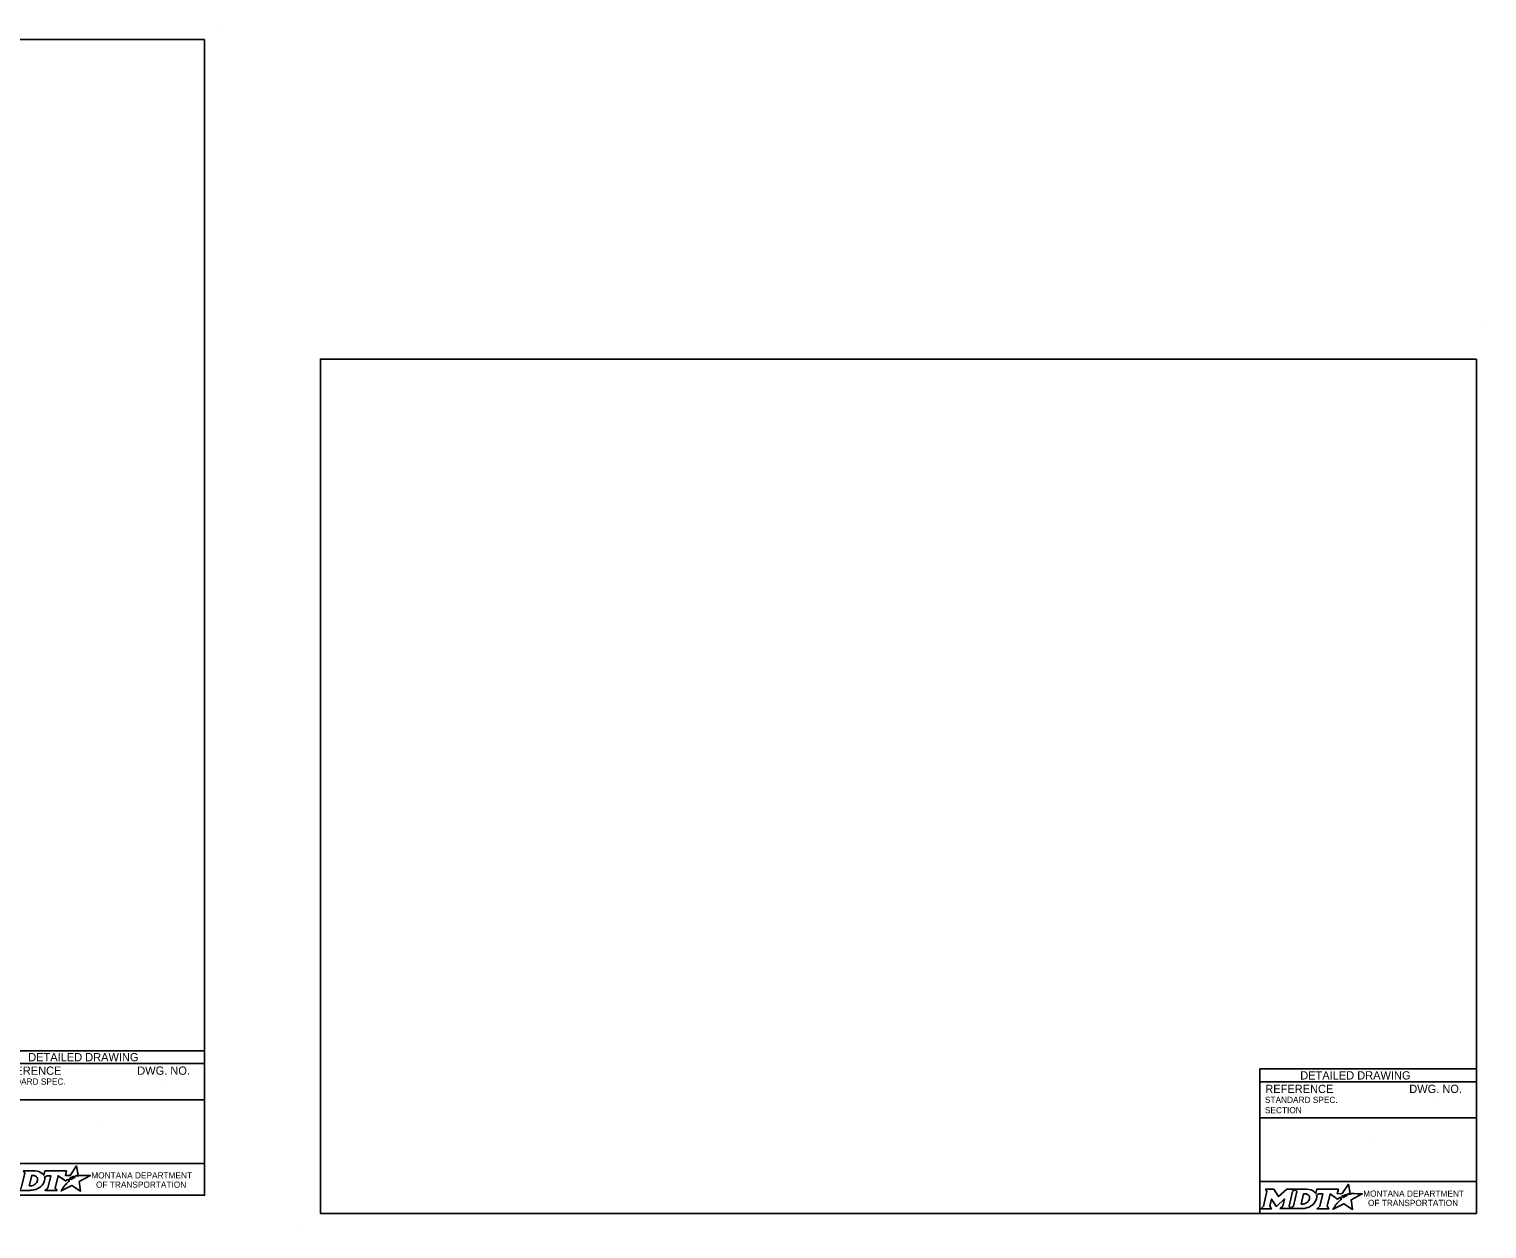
# Model space of a CAD drawing. Extents: x 49991.4 to 50021, y 49987.6 to 50011.4.
# Drawn here: x 50006.92 to 50021.04, y 49999.74 to 50011.36 of the extents above; entities that cross this region are included whole.
import ezdxf

# ---------------------------------------------------------------- set-up
doc = ezdxf.new("R2010")
doc.units = 0
for name, color, linetype in [('Default', 7, 'Continuous'), ('Level 1', 7, 'Continuous'), ('Level 2', 7, 'Continuous'), ('Level 4', 7, 'Continuous')]:
    doc.layers.add(name, color=color, linetype=linetype)

msp = doc.modelspace()

# ---------------------------------------------------------------- linework, layer by layer
at = {"layer": 'Default'}
for points in [[(50019.7, 50000.068), (50019.69, 50000.074), (50019.702, 50000.076), (50019.713, 50000.078), (50019.696, 50000.168), (50019.636, 50000.077), (50019.589, 50000.076), (50019.599, 50000.12), (50019.39, 50000.121), (50019.38, 50000.078), (50019.374, 50000.086)], [(50018.893, 50000.121), (50018.907, 50000.097), (50018.874, 49999.954), (50018.848, 49999.931), (50018.95, 49999.931), (50018.936, 49999.954), (50018.952, 50000.024), (50018.996, 49999.955), (50019.002, 49999.955), (50019.077, 50000.025), (50019.06, 49999.954), (50019.035, 49999.932), (50019.137, 49999.932), (50019.123, 49999.955), (50019.156, 50000.097)], [(50019.156, 50000.097), (50019.182, 50000.121), (50019.099, 50000.121), (50019.02, 50000.048), (50018.975, 50000.12), (50018.893, 50000.121)], [(50019.295, 50000.121), (50019.182, 50000.121), (50019.196, 50000.098), (50019.163, 49999.954), (50019.137, 49999.932), (50019.248, 49999.932)], [(50019.319, 50000.034), (50019.318, 50000.026), (50019.315, 50000.017), (50019.311, 50000.008), (50019.305, 50000.001), (50019.299, 49999.994), (50019.291, 49999.988), (50019.282, 49999.983), (50019.273, 49999.979), (50019.264, 49999.977), (50019.255, 49999.976), (50019.239, 49999.976), (50019.263, 50000.076), (50019.279, 50000.076), (50019.286, 50000.075), (50019.294, 50000.073), (50019.301, 50000.07), (50019.307, 50000.066), (50019.311, 50000.061), (50019.315, 50000.055), (50019.318, 50000.049), (50019.319, 50000.042), (50019.32, 50000.038), (50019.319, 50000.034)], [(50019.387, 50000.062), (50019.411, 50000.075), (50019.448, 50000.075), (50019.42, 49999.954), (50019.392, 49999.931), (50019.508, 49999.931), (50019.491, 49999.954), (50019.52, 50000.075), (50019.591, 50000.023), (50019.612, 50000.038), (50019.632, 50000.027)], [(50019.576, 49999.971), (50019.561, 49999.947), (50019.556, 49999.939), (50019.55, 49999.931), (50019.548, 49999.926), (50019.653, 49999.979), (50019.737, 49999.924), (50019.724, 50000.017), (50019.831, 50000.075), (50019.782, 50000.076), (50019.751, 50000.077), (50019.731, 50000.077), (50019.724, 50000.075), (50019.719, 50000.074), (50019.711, 50000.072), (50019.7, 50000.068)], [(50019.65, 50000.04), (50019.648, 50000.039), (50019.629, 50000.048), (50019.639, 50000.054), (50019.644, 50000.056), (50019.652, 50000.06), (50019.658, 50000.063), (50019.666, 50000.066), (50019.673, 50000.068), (50019.685, 50000.061), (50019.681, 50000.059), (50019.676, 50000.056), (50019.672, 50000.054), (50019.667, 50000.051), (50019.665, 50000.05), (50019.662, 50000.049), (50019.66, 50000.047), (50019.658, 50000.046), (50019.655, 50000.044), (50019.652, 50000.042), (50019.65, 50000.04)], [(50019.293, 49999.939), (50019.302, 49999.942), (50019.315, 49999.947), (50019.335, 49999.958)], [(50019.59, 49999.987), (50019.59, 49999.987)]]:
    msp.add_lwpolyline(points, dxfattribs=at)
for centre, radius, start, end in [((50019.319, 50000.042), 0.0709, 339.5329, 15.8582), ((50019.274, 50000.059), 0.118, 300.9103, 339.1383)]:
    msp.add_arc(centre, radius, start, end, dxfattribs=at)
for centre, major_axis, ratio, start_param, end_param in [((50019.293, 50000.073), (0.0834, -0.0037), 0.568097, 0.61298, 1.570796), ((50019.349, 50000.081), (0.0361, -0.0295), 0.469099, 1.225588, 1.570796), ((50019.621, 50000.017), (-0.0112, -0.0097), 0.021651, 3.157348, 6.283185), ((50019.248, 50000.08), (0, 0.148), 0.987302, 3.139398, 3.456847), ((50019.583, 49999.979), (-0.00694, -0.00806), 0.008222, 0, 3.137361), ((50019.6, 49999.997), (-0.0098, -0.0102), 0.016458, 3.141593, 6.279097)]:
    msp.add_ellipse(centre, major_axis=major_axis, ratio=ratio, start_param=start_param, end_param=end_param, dxfattribs=at)
at = {"layer": 'Level 1'}
for p, q in [((50008.765, 50011.363), (50008.765, 50011.363)), ((50021.038, 50008.524), (50021.038, 50008.524)), ((50009.537, 49999.736), (50009.537, 49999.736))]:
    msp.add_line(p, q, dxfattribs=at)
for points in [[(50008.615, 50011.263), (50000.336, 50011.263), (50000.336, 50000.062), (50008.615, 50000.062)], [(50020.938, 50008.165), (50009.737, 50008.165), (50009.737, 49999.886), (50020.938, 49999.886)]]:
    msp.add_lwpolyline(points, close=True, dxfattribs=at)
at = {"layer": 'Level 2'}
for p, q in [((50008.615, 50001.462), (50006.515, 50001.462)), ((50008.615, 50001.337), (50006.515, 50001.337)), ((50007.009, 50001.063), (50007.009, 50001.063)), ((50008.251, 50001.122), (50008.251, 50001.122)), ((50008.615, 50000.987), (50006.515, 50000.987)), ((50007.565, 50000.738), (50007.565, 50000.738)), ((50008.615, 50000.369), (50006.515, 50000.369))]:
    msp.add_line(p, q, dxfattribs=at)
for points in [[(50007.377, 50000.245), (50007.367, 50000.25), (50007.378, 50000.253), (50007.39, 50000.255), (50007.373, 50000.345), (50007.313, 50000.254), (50007.266, 50000.253), (50007.276, 50000.297), (50007.067, 50000.297), (50007.057, 50000.255), (50007.051, 50000.263)], [(50006.972, 50000.297), (50006.859, 50000.297), (50006.873, 50000.275), (50006.839, 50000.131), (50006.814, 50000.108), (50006.925, 50000.108)], [(50006.996, 50000.211), (50006.995, 50000.203), (50006.992, 50000.193), (50006.988, 50000.185), (50006.982, 50000.178), (50006.976, 50000.171), (50006.968, 50000.164), (50006.959, 50000.16), (50006.95, 50000.156), (50006.941, 50000.154), (50006.932, 50000.153), (50006.916, 50000.153), (50006.94, 50000.253), (50006.956, 50000.253), (50006.963, 50000.252), (50006.971, 50000.25), (50006.977, 50000.247), (50006.983, 50000.243), (50006.988, 50000.238), (50006.992, 50000.232), (50006.995, 50000.226), (50006.996, 50000.218), (50006.996, 50000.215), (50006.996, 50000.211)], [(50007.064, 50000.238), (50007.088, 50000.251), (50007.125, 50000.251), (50007.097, 50000.131), (50007.069, 50000.108), (50007.185, 50000.108), (50007.168, 50000.131), (50007.196, 50000.251), (50007.268, 50000.2), (50007.289, 50000.215), (50007.309, 50000.204)], [(50007.253, 50000.148), (50007.237, 50000.124), (50007.233, 50000.116), (50007.227, 50000.107), (50007.225, 50000.103), (50007.33, 50000.156), (50007.414, 50000.101), (50007.401, 50000.194), (50007.508, 50000.252), (50007.458, 50000.253), (50007.428, 50000.253), (50007.407, 50000.254), (50007.401, 50000.252), (50007.396, 50000.251), (50007.387, 50000.249), (50007.377, 50000.245)], [(50007.267, 50000.164), (50007.267, 50000.164)], [(50007.327, 50000.217), (50007.324, 50000.215), (50007.306, 50000.225), (50007.316, 50000.231), (50007.32, 50000.233), (50007.329, 50000.237), (50007.335, 50000.239), (50007.343, 50000.243), (50007.35, 50000.245), (50007.362, 50000.238), (50007.358, 50000.236), (50007.353, 50000.233), (50007.349, 50000.231), (50007.344, 50000.228), (50007.342, 50000.227), (50007.339, 50000.225), (50007.337, 50000.224), (50007.334, 50000.222), (50007.332, 50000.221), (50007.329, 50000.219), (50007.327, 50000.217)], [(50006.97, 50000.116), (50006.979, 50000.118), (50006.992, 50000.124), (50007.012, 50000.135)]]:
    msp.add_lwpolyline(points, dxfattribs=at)
for centre, radius, start, end in [((50006.951, 50000.236), 0.118, 300.9103, 339.1383), ((50006.995, 50000.219), 0.0709, 339.5329, 15.8582)]:
    msp.add_arc(centre, radius, start, end, dxfattribs=at)
for centre, major_axis, ratio, start_param, end_param in [((50006.97, 50000.25), (0.0834, -0.0037), 0.568097, 0.61298, 1.570796), ((50007.026, 50000.257), (0.0361, -0.0295), 0.469099, 1.225588, 1.570796), ((50007.26, 50000.156), (-0.00694, -0.00806), 0.008222, 0, 3.137361), ((50007.276, 50000.174), (-0.0098, -0.0102), 0.016458, 3.141593, 6.279097), ((50007.297, 50000.194), (-0.0112, -0.0097), 0.021651, 3.157348, 6.283185), ((50006.925, 50000.257), (0, 0.148), 0.987302, 3.139398, 3.456847)]:
    msp.add_ellipse(centre, major_axis=major_axis, ratio=ratio, start_param=start_param, end_param=end_param, dxfattribs=at)
at = {"layer": 'Level 4'}
for p, q in [((50020.938, 50001.286), (50018.838, 50001.286)), ((50018.838, 50001.286), (50018.838, 49999.886)), ((50020.938, 50001.161), (50018.838, 50001.161)), ((50019.332, 50000.886), (50019.332, 50000.886)), ((50020.574, 50000.946), (50020.574, 50000.946)), ((50020.938, 50000.811), (50018.838, 50000.811)), ((50019.888, 50000.562), (50019.888, 50000.562)), ((50020.938, 50000.193), (50018.838, 50000.193))]:
    msp.add_line(p, q, dxfattribs=at)

# ---------------------------------------------------------------- texts
at = {"layer": 'Default'}
for s, p in [('MONTANA DEPARTMENT', (50019.84, 50000.047)), ('OF TRANSPORTATION', (50019.886, 49999.957))]:
    msp.add_text(s, height=0.06, rotation=360, dxfattribs=at).set_placement(p)
at = {"layer": 'Level 2'}
for s, height, p in [('DETAILED DRAWING', 0.0799, (50006.906, 50001.36)), ('REFERENCE', 0.08, (50006.568, 50001.229)), ('DWG. NO.', 0.08, (50007.962, 50001.229)), ('STANDARD SPEC.', 0.06, (50006.565, 50001.133))]:
    msp.add_text(s, height=height, dxfattribs=at).set_placement(p)
for s, p in [('MONTANA DEPARTMENT', (50007.517, 50000.224)), ('OF TRANSPORTATION', (50007.563, 50000.134))]:
    msp.add_text(s, height=0.06, rotation=360, dxfattribs=at).set_placement(p)
at = {"layer": 'Level 4'}
for s, height, p in [('DETAILED DRAWING', 0.0799, (50019.23, 50001.183)), ('STANDARD SPEC.', 0.06, (50018.888, 50000.956)), ('REFERENCE', 0.08, (50018.891, 50001.052)), ('DWG. NO.', 0.08, (50020.286, 50001.052)), ('SECTION', 0.06, (50018.888, 50000.856))]:
    msp.add_text(s, height=height, dxfattribs=at).set_placement(p)

doc.saveas('drawing.dxf')
